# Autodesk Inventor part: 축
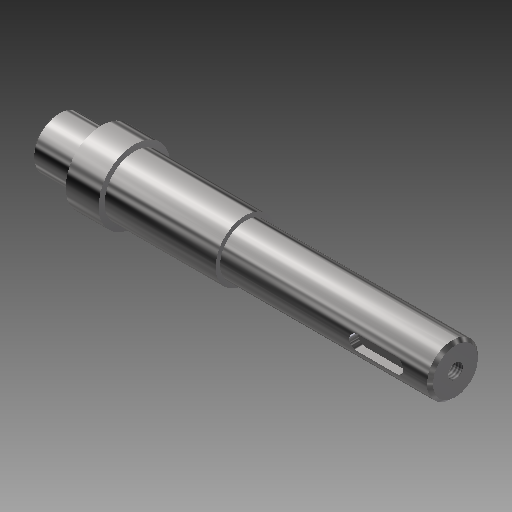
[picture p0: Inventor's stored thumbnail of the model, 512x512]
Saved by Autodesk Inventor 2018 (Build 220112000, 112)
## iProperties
Created: 2015-09
Part Number: 축
Material: 강철, 연강
Document SubType Name: Modeling
Designer: mduedu
Density: 7.86 g/cm^3
Mass: 263.424 g
Surface Area: 86.4309 cm^2
Volume: 33.5145 cm^3
Appearance: 반광택
Author: mduedu
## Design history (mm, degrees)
sketch "스케치1"
  geometry: L1 (-66.5, 0)-(66.5, 0); L2 (-66.5, 0)-(-66.5, 8.5); L3 (-66.5, 8.5)-(-51.5, 8.5); L4 (-51.5, 8.5)-(-51.5, 12); L5 (-51.5, 12)-(-40.5, 12); L6 (-40.5, 12)-(-40.5, 10); L7 (-40.5, 10)-(-3.5, 10); L8 (-3.5, 10)-(-3.5, 8.5); L9 (-3.5, 8.5)-(66.5, 8.5); L10 (66.5, 8.5)-(66.5, 0); 2 further points
  constraints: 20 end point, 5 parallel, 2 horizontal, 2 perpendicular, 1 coincident, 1 midpoint, 1 vertical
  dimensions: "d0" = 133 distance of L1.start L1.end; "d2" = 11 distance of L4.end L5.end; "d3" = 37 distance of L6.end L7.end; "d4" = 70 distance of L8.end L9.end; "d5" = 17 diameter of L3 L1; "d6" = 17 diameter of L9 L1; "d7" = 20 diameter of L7 L1; "d8" = 24 diameter of L5 L1
revolve "회전1" sketch "스케치1" stored, may be unused: angle "d9" = 90 deg
node "작업 평면1"
sketch "스케치2"
  geometry: L1 (10.5, 2.5)-(23.5, 2.5); L2 (23.5, -2.5)-(10.5, -2.5); L3 (10.5, 2.5)-(23.5, -2.5); L4 (23.5, 2.5)-(10.5, -2.5); L5 (35, -8.5)-(35, 8.5) reference; A1 r 2.5 centre (10.5, 0) between (10.5, 2.5) and (10.5, -2.5); A2 r 2.5 centre (23.5, 0) between (23.5, -2.5) and (23.5, 2.5); 2 further points
  constraints: 8 end point, 4 point on circle, 4 tangent, 2 centre point, 2 midpoint, 1 horizontal, 1 horizontal alignment, 1 parallel
  dimensions: "d10" = 18 dimension on A2 A1; "d12" = 9 distance edge to line of A2 L5; "d13" = 5 distance between parallel lines of L2 L1
extrude "돌출1" cut sketch "스케치2" distance "d14" = 3; taper "d15" = 0 deg
node "작업 평면2"
sketch "스케치4"
  geometry: L1 (9.5, -3)-(-6.5, -3); L2 (-6.5, 3)-(9.5, 3); L3 (-18.5, 10)-(-18.5, -10) reference; A1 r 3 centre (-6.5, 0) between (-6.5, 3) and (-6.5, -3); A2 r 3 centre (9.5, 0) between (9.5, -3) and (9.5, 3); 1 further point
  constraints: 4 end point, 4 point on circle, 4 tangent, 2 centre point, 1 horizontal, 1 horizontal alignment, 1 parallel
  dimensions: "d16" = 22 dimension on A1 A2; "d18" = 6 distance between parallel lines of L2 L1; "d19" = 9 distance edge to line of A1 L3
extrude "돌출2" cut sketch "스케치4" distance "d20" = 3.5; taper "d21" = 0 deg
sketch "스케치5"
  geometry: L1 (-3.5, 8.5)-(66.5, 8.5) reference; L2 (-3.5, -8.5)-(66.5, -8.5) reference; L3 (40.5, 8.5)-(40.5, -8.5); L4 (40.5, -6.5)-(38.5, -8.5); L5 (40.5, -8.5)-(38.5, -8.5); L6 (40.5, -8.5)-(40.5, -6.5); L7 (-3.5, -10)-(-3.5, 10) reference; 1 further point
  constraints: 8 end point, 4 point on line, 1 collinear, 1 perpendicular
  dimensions: "d22" = 4 diameter of L4.end L3; "d24" = 45 deg angle of L3 L4; "d26" = 44 distance between parallel lines of L3 L7
revolve "회전2" sketch "스케치5" stored, may be unused: angle "d27" = 90 deg
chamfer "모따기1" distance "d28" = 1; stored, may be unused: second distance "d29" = 2, angle "d30" = 45 deg
sketch "스케치6"
  geometry: L1 (40.5, -6.5)-(38.5, -8.5) reference; L2 (40.5, -6.5)-(42.5, -8.5) reference; 2 further points
  constraints: 1 coincident
hole "구멍1" diameter "d33" = 4.917; stored, may be unused: countersink angle "d37" = 90 deg, drill point angle "d39" = 118 deg; dims "d34" = 12, "d35" = 4, "d36" = 2, "d38" = 15, "d42" = 10, "d43" = 10
node "솔리드1"
